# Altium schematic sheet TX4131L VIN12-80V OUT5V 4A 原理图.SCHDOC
size A; SheetNumber: 0; SheetTotal: 0
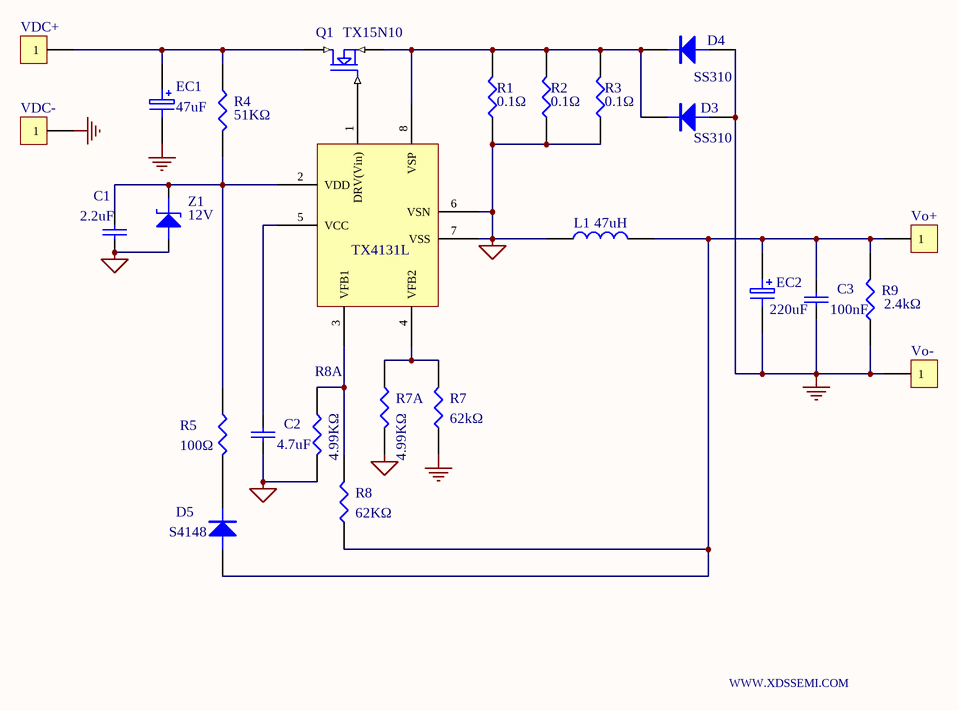
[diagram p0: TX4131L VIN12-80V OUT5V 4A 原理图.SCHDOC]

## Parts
C1  2.2uF  [R0805]
C2  4.7uF  [R1206]
C3  100nF  [R1206]
D3  SS310  [SMB]
D4  SS310  [SMB]
D5  S4148
EC1  47uF  [c10*16]
EC2  220uF  [C10*16]
L1  47uH  [L12*12]
Q1  TX15N10  [TO252]
R1  0.1Ω  [R1206]
R2  0.1Ω  [R1206]
R3  0.1Ω  [R1206]
R4  51KΩ  [R1206]
R5  100Ω  [R1206]
R7  62kΩ  [r0805]
R7A  4.99KΩ  [r0805]
R8  62KΩ  [r0805]
R8A  4.99KΩ  [r0805]
R9  2.4kΩ  [R0805]
TX4131L  TX4131  (value not drawn)
VDC+  (no value)  [pad]
VDC-  (no value)
Vo+  (no value)  [pad]
Vo-  (no value)  [pad]
Z1  12V

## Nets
GND: C3.2 D3.1(A) D4.1(A) EC1.2 EC2.2 R7.1 R9.1 VDC-.1 Vo-.1
SGND: C1.2 C2.2 L1.1 R1.1 R2.1 R3.1 R7A.2 R8A.2 TX4131L.6(VSN) TX4131L.7(VSS) Z1.1(A)
NetC1_1: C1.1 R4.2 R5.1 TX4131L.2(VDD) Z1.2(K)
NetC2_1: C2.1 TX4131L.5(VCC)
NetC3_1: C3.1 D5.1(A) EC2.1 L1.2 R8.1 R9.2 Vo+.1
NetD3_2: D3.2(K) D4.2(K) Q1.3(S) R1.2 R2.2 R3.2 TX4131L.8(VSP)
NetD5_2: D5.2(K) R5.2
NetEC1_1: EC1.1 Q1.2(D) R4.1 VDC+.1
NetQ1_1: Q1.1(G) TX4131L.1(DRV(Vin))
NetR7_2: R7.2 R7A.1 TX4131L.4(VFB2)
NetR8_2: R8.2 R8A.1 TX4131L.3(VFB1)

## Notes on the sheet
- WWW.XDSSEMI.COM

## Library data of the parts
C1-C3 = CAP: Capacitor
D3-D5 = DIODE
EC1 EC2 = ELECTRO1: Electrolytic Capacitor
L1 = INDUCTOR
Q1 = MOSFET N
R1-R5 R7 R7A R8 R8A R9 = RES1
VDC+ VDC- Vo+ Vo- = CON1: Connector
Z1 = ZENER2: Zener Diode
